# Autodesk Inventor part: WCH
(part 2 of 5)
hole "Díra1151" diameter "d10358" = 8.19608; stored, may be unused: countersink angle "d10362" = 90 deg, drill point angle "d10364" = 0 deg; dims "d10356" = 351, "d10357" = 76, "d10359" = 6, "d10360" = 4, "d10361" = 2, "d10363" = 8
hole "Díra1152" diameter "d10367" = 8.47059; stored, may be unused: countersink angle "d10371" = 90 deg, drill point angle "d10373" = 0 deg; dims "d10365" = 10, "d10366" = 87, "d10368" = 6, "d10369" = 4, "d10370" = 2, "d10372" = 8
hole "Díra1153" diameter "d10376" = 9.01961; stored, may be unused: countersink angle "d10380" = 90 deg, drill point angle "d10382" = 0 deg; dims "d10374" = 21, "d10375" = 87, "d10377" = 6, "d10378" = 4, "d10379" = 2, "d10381" = 8
hole "Díra1154" diameter "d10385" = 9.84314; stored, may be unused: countersink angle "d10389" = 90 deg, drill point angle "d10391" = 0 deg; dims "d10383" = 32, "d10384" = 87, "d10386" = 6, "d10387" = 4, "d10388" = 2, "d10390" = 8
hole "Díra1155" diameter "d10394" = 10; stored, may be unused: countersink angle "d10398" = 90 deg, drill point angle "d10400" = 0 deg; dims "d10392" = 43, "d10393" = 87, "d10395" = 6, "d10396" = 4, "d10397" = 2, "d10399" = 8
hole "Díra1156" diameter "d10403" = 10; stored, may be unused: countersink angle "d10407" = 90 deg, drill point angle "d10409" = 0 deg; dims "d10401" = 54, "d10402" = 87, "d10404" = 6, "d10405" = 4, "d10406" = 2, "d10408" = 8
hole "Díra1157" diameter "d10412" = 10; stored, may be unused: countersink angle "d10416" = 90 deg, drill point angle "d10418" = 0 deg; dims "d10410" = 65, "d10411" = 87, "d10413" = 6, "d10414" = 4, "d10415" = 2, "d10417" = 8
hole "Díra1158" diameter "d10421" = 10; stored, may be unused: countersink angle "d10425" = 90 deg, drill point angle "d10427" = 0 deg; dims "d10419" = 76, "d10420" = 87, "d10422" = 6, "d10423" = 4, "d10424" = 2, "d10426" = 8
hole "Díra1159" diameter "d10430" = 10; stored, may be unused: countersink angle "d10434" = 90 deg, drill point angle "d10436" = 0 deg; dims "d10428" = 87, "d10429" = 87, "d10431" = 6, "d10432" = 4, "d10433" = 2, "d10435" = 8
hole "Díra1160" diameter "d10439" = 10; stored, may be unused: countersink angle "d10443" = 90 deg, drill point angle "d10445" = 0 deg; dims "d10437" = 98, "d10438" = 87, "d10440" = 6, "d10441" = 4, "d10442" = 2, "d10444" = 8
hole "Díra1161" diameter "d10448" = 10; stored, may be unused: countersink angle "d10452" = 90 deg, drill point angle "d10454" = 0 deg; dims "d10446" = 109, "d10447" = 87, "d10449" = 6, "d10450" = 4, "d10451" = 2, "d10453" = 8
hole "Díra1162" diameter "d10457" = 10; stored, may be unused: countersink angle "d10461" = 90 deg, drill point angle "d10463" = 0 deg; dims "d10455" = 120, "d10456" = 87, "d10458" = 6, "d10459" = 4, "d10460" = 2, "d10462" = 8
hole "Díra1163" diameter "d10466" = 8.98039; stored, may be unused: countersink angle "d10470" = 90 deg, drill point angle "d10472" = 0 deg; dims "d10464" = 131, "d10465" = 87, "d10467" = 6, "d10468" = 4, "d10469" = 2, "d10471" = 8
hole "Díra1164" diameter "d10475" = 5.92157; stored, may be unused: countersink angle "d10479" = 90 deg, drill point angle "d10481" = 0 deg; dims "d10473" = 142, "d10474" = 87, "d10476" = 6, "d10477" = 4, "d10478" = 2, "d10480" = 8
hole "Díra1165" diameter "d10484" = 6.54902; stored, may be unused: countersink angle "d10488" = 90 deg, drill point angle "d10490" = 0 deg; dims "d10482" = 153, "d10483" = 87, "d10485" = 6, "d10486" = 4, "d10487" = 2, "d10489" = 8
hole "Díra1166" diameter "d10493" = 3.96078; stored, may be unused: countersink angle "d10497" = 90 deg, drill point angle "d10499" = 0 deg; dims "d10491" = 164, "d10492" = 87, "d10494" = 6, "d10495" = 4, "d10496" = 2, "d10498" = 8
hole "Díra1167" diameter "d10502" = 1.09804; stored, may be unused: countersink angle "d10506" = 90 deg, drill point angle "d10508" = 0 deg; dims "d10500" = 175, "d10501" = 87, "d10503" = 6, "d10504" = 4, "d10505" = 2, "d10507" = 8
hole "Díra1168" diameter "d10511" = 0.5098; stored, may be unused: countersink angle "d10515" = 90 deg, drill point angle "d10517" = 0 deg; dims "d10509" = 186, "d10510" = 87, "d10512" = 6, "d10513" = 4, "d10514" = 2, "d10516" = 8
hole "Díra1169" diameter "d10520" = 1.33333; stored, may be unused: countersink angle "d10524" = 90 deg, drill point angle "d10526" = 0 deg; dims "d10518" = 197, "d10519" = 87, "d10521" = 6, "d10522" = 4, "d10523" = 2, "d10525" = 8
hole "Díra1170" diameter "d10529" = 2.39216; stored, may be unused: countersink angle "d10533" = 90 deg, drill point angle "d10535" = 0 deg; dims "d10527" = 208, "d10528" = 87, "d10530" = 6, "d10531" = 4, "d10532" = 2, "d10534" = 8
hole "Díra1171" diameter "d10538" = 3.72549; stored, may be unused: countersink angle "d10542" = 90 deg, drill point angle "d10544" = 0 deg; dims "d10536" = 219, "d10537" = 87, "d10539" = 6, "d10540" = 4, "d10541" = 2, "d10543" = 8
hole "Díra1172" diameter "d10547" = 6; stored, may be unused: countersink angle "d10551" = 90 deg, drill point angle "d10553" = 0 deg; dims "d10545" = 230, "d10546" = 87, "d10548" = 6, "d10549" = 4, "d10550" = 2, "d10552" = 8
hole "Díra1173" diameter "d10556" = 1.13725; stored, may be unused: countersink angle "d10560" = 90 deg, drill point angle "d10562" = 0 deg; dims "d10554" = 241, "d10555" = 87, "d10557" = 6, "d10558" = 4, "d10559" = 2, "d10561" = 8
hole "Díra1174" diameter "d10565" = 1.13725; stored, may be unused: countersink angle "d10569" = 90 deg, drill point angle "d10571" = 0 deg; dims "d10563" = 252, "d10564" = 87, "d10566" = 6, "d10567" = 4, "d10568" = 2, "d10570" = 8
hole "Díra1175" diameter "d10574" = 7.56863; stored, may be unused: countersink angle "d10578" = 90 deg, drill point angle "d10580" = 0 deg; dims "d10572" = 263, "d10573" = 87, "d10575" = 6, "d10576" = 4, "d10577" = 2, "d10579" = 8
hole "Díra1176" diameter "d10583" = 10; stored, may be unused: countersink angle "d10587" = 90 deg, drill point angle "d10589" = 0 deg; dims "d10581" = 274, "d10582" = 87, "d10584" = 6, "d10585" = 4, "d10586" = 2, "d10588" = 8
hole "Díra1177" diameter "d10592" = 10; stored, may be unused: countersink angle "d10596" = 90 deg, drill point angle "d10598" = 0 deg; dims "d10590" = 285, "d10591" = 87, "d10593" = 6, "d10594" = 4, "d10595" = 2, "d10597" = 8
hole "Díra1178" diameter "d10601" = 9.92157; stored, may be unused: countersink angle "d10605" = 90 deg, drill point angle "d10607" = 0 deg; dims "d10599" = 296, "d10600" = 87, "d10602" = 6, "d10603" = 4, "d10604" = 2, "d10606" = 8
hole "Díra1179" diameter "d10610" = 9.2549; stored, may be unused: countersink angle "d10614" = 90 deg, drill point angle "d10616" = 0 deg; dims "d10608" = 307, "d10609" = 87, "d10611" = 6, "d10612" = 4, "d10613" = 2, "d10615" = 8
hole "Díra1180" diameter "d10619" = 8.58823; stored, may be unused: countersink angle "d10623" = 90 deg, drill point angle "d10625" = 0 deg; dims "d10617" = 318, "d10618" = 87, "d10620" = 6, "d10621" = 4, "d10622" = 2, "d10624" = 8
hole "Díra1181" diameter "d10628" = 7.41176; stored, may be unused: countersink angle "d10632" = 90 deg, drill point angle "d10634" = 0 deg; dims "d10626" = 329, "d10627" = 87, "d10629" = 6, "d10630" = 4, "d10631" = 2, "d10633" = 8
hole "Díra1182" diameter "d10637" = 6.7451; stored, may be unused: countersink angle "d10641" = 90 deg, drill point angle "d10643" = 0 deg; dims "d10635" = 340, "d10636" = 87, "d10638" = 6, "d10639" = 4, "d10640" = 2, "d10642" = 8
hole "Díra1183" diameter "d10646" = 8.43137; stored, may be unused: countersink angle "d10650" = 90 deg, drill point angle "d10652" = 0 deg; dims "d10644" = 351, "d10645" = 87, "d10647" = 6, "d10648" = 4, "d10649" = 2, "d10651" = 8
hole "Díra1184" diameter "d10655" = 6.66667; stored, may be unused: countersink angle "d10659" = 90 deg, drill point angle "d10661" = 0 deg; dims "d10653" = 10, "d10654" = 98, "d10656" = 6, "d10657" = 4, "d10658" = 2, "d10660" = 8
hole "Díra1185" diameter "d10664" = 8.47059; stored, may be unused: countersink angle "d10668" = 90 deg, drill point angle "d10670" = 0 deg; dims "d10662" = 21, "d10663" = 98, "d10665" = 6, "d10666" = 4, "d10667" = 2, "d10669" = 8
hole "Díra1186" diameter "d10673" = 10; stored, may be unused: countersink angle "d10677" = 90 deg, drill point angle "d10679" = 0 deg; dims "d10671" = 32, "d10672" = 98, "d10674" = 6, "d10675" = 4, "d10676" = 2, "d10678" = 8
hole "Díra1187" diameter "d10682" = 10; stored, may be unused: countersink angle "d10686" = 90 deg, drill point angle "d10688" = 0 deg; dims "d10680" = 43, "d10681" = 98, "d10683" = 6, "d10684" = 4, "d10685" = 2, "d10687" = 8
hole "Díra1188" diameter "d10691" = 10; stored, may be unused: countersink angle "d10695" = 90 deg, drill point angle "d10697" = 0 deg; dims "d10689" = 54, "d10690" = 98, "d10692" = 6, "d10693" = 4, "d10694" = 2, "d10696" = 8
hole "Díra1189" diameter "d10700" = 10; stored, may be unused: countersink angle "d10704" = 90 deg, drill point angle "d10706" = 0 deg; dims "d10698" = 65, "d10699" = 98, "d10701" = 6, "d10702" = 4, "d10703" = 2, "d10705" = 8
hole "Díra1190" diameter "d10709" = 10; stored, may be unused: countersink angle "d10713" = 90 deg, drill point angle "d10715" = 0 deg; dims "d10707" = 76, "d10708" = 98, "d10710" = 6, "d10711" = 4, "d10712" = 2, "d10714" = 8
hole "Díra1191" diameter "d10718" = 10; stored, may be unused: countersink angle "d10722" = 90 deg, drill point angle "d10724" = 0 deg; dims "d10716" = 87, "d10717" = 98, "d10719" = 6, "d10720" = 4, "d10721" = 2, "d10723" = 8
hole "Díra1192" diameter "d10727" = 10; stored, may be unused: countersink angle "d10731" = 90 deg, drill point angle "d10733" = 0 deg; dims "d10725" = 98, "d10726" = 98, "d10728" = 6, "d10729" = 4, "d10730" = 2, "d10732" = 8
hole "Díra1193" diameter "d10736" = 10; stored, may be unused: countersink angle "d10740" = 90 deg, drill point angle "d10742" = 0 deg; dims "d10734" = 109, "d10735" = 98, "d10737" = 6, "d10738" = 4, "d10739" = 2, "d10741" = 8
hole "Díra1194" diameter "d10745" = 8.90196; stored, may be unused: countersink angle "d10749" = 90 deg, drill point angle "d10751" = 0 deg; dims "d10743" = 120, "d10744" = 98, "d10746" = 6, "d10747" = 4, "d10748" = 2, "d10750" = 8
hole "Díra1195" diameter "d10754" = 5.84314; stored, may be unused: countersink angle "d10758" = 90 deg, drill point angle "d10760" = 0 deg; dims "d10752" = 131, "d10753" = 98, "d10755" = 6, "d10756" = 4, "d10757" = 2, "d10759" = 8
hole "Díra1196" diameter "d10763" = 5.68628; stored, may be unused: countersink angle "d10767" = 90 deg, drill point angle "d10769" = 0 deg; dims "d10761" = 142, "d10762" = 98, "d10764" = 6, "d10765" = 4, "d10766" = 2, "d10768" = 8
hole "Díra1197" diameter "d10772" = 4.07843; stored, may be unused: countersink angle "d10776" = 90 deg, drill point angle "d10778" = 0 deg; dims "d10770" = 153, "d10771" = 98, "d10773" = 6, "d10774" = 4, "d10775" = 2, "d10777" = 8
hole "Díra1198" diameter "d10781" = 1.01961; stored, may be unused: countersink angle "d10785" = 90 deg, drill point angle "d10787" = 0 deg; dims "d10779" = 164, "d10780" = 98, "d10782" = 6, "d10783" = 4, "d10784" = 2, "d10786" = 8
hole "Díra1199" diameter "d10790" = 0.07843; stored, may be unused: countersink angle "d10794" = 90 deg, drill point angle "d10796" = 0 deg; dims "d10788" = 175, "d10789" = 98, "d10791" = 6, "d10792" = 4, "d10793" = 2, "d10795" = 8
hole "Díra1200" diameter "d10799" = 0.27451; stored, may be unused: countersink angle "d10803" = 90 deg, drill point angle "d10805" = 0 deg; dims "d10797" = 186, "d10798" = 98, "d10800" = 6, "d10801" = 4, "d10802" = 2, "d10804" = 8
hole "Díra1201" diameter "d10808" = 1.4902; stored, may be unused: countersink angle "d10812" = 90 deg, drill point angle "d10814" = 0 deg; dims "d10806" = 197, "d10807" = 98, "d10809" = 6, "d10810" = 4, "d10811" = 2, "d10813" = 8
hole "Díra1202" diameter "d10817" = 5.09804; stored, may be unused: countersink angle "d10821" = 90 deg, drill point angle "d10823" = 0 deg; dims "d10815" = 208, "d10816" = 98, "d10818" = 6, "d10819" = 4, "d10820" = 2, "d10822" = 8
hole "Díra1203" diameter "d10826" = 7.68628; stored, may be unused: countersink angle "d10830" = 90 deg, drill point angle "d10832" = 0 deg; dims "d10824" = 219, "d10825" = 98, "d10827" = 6, "d10828" = 4, "d10829" = 2, "d10831" = 8
hole "Díra1204" diameter "d10835" = 6.15686; stored, may be unused: countersink angle "d10839" = 90 deg, drill point angle "d10841" = 0 deg; dims "d10833" = 230, "d10834" = 98, "d10836" = 6, "d10837" = 4, "d10838" = 2, "d10840" = 8
hole "Díra1205" diameter "d10844" = 0.31372; stored, may be unused: countersink angle "d10848" = 90 deg, drill point angle "d10850" = 0 deg; dims "d10842" = 241, "d10843" = 98, "d10845" = 6, "d10846" = 4, "d10847" = 2, "d10849" = 8
hole "Díra1206" diameter "d10853" = 2.19608; stored, may be unused: countersink angle "d10857" = 90 deg, drill point angle "d10859" = 0 deg; dims "d10851" = 252, "d10852" = 98, "d10854" = 6, "d10855" = 4, "d10856" = 2, "d10858" = 8
hole "Díra1207" diameter "d10862" = 7.15033; stored, may be unused: countersink angle "d10866" = 90 deg, drill point angle "d10868" = 0 deg; dims "d10860" = 263, "d10861" = 98, "d10863" = 6, "d10864" = 4, "d10865" = 2, "d10867" = 8
hole "Díra1208" diameter "d10871" = 9.80392; stored, may be unused: countersink angle "d10875" = 90 deg, drill point angle "d10877" = 0 deg; dims "d10869" = 274, "d10870" = 98, "d10872" = 6, "d10873" = 4, "d10874" = 2, "d10876" = 8
hole "Díra1209" diameter "d10880" = 10; stored, may be unused: countersink angle "d10884" = 90 deg, drill point angle "d10886" = 0 deg; dims "d10878" = 285, "d10879" = 98, "d10881" = 6, "d10882" = 4, "d10883" = 2, "d10885" = 8
hole "Díra1210" diameter "d10889" = 10; stored, may be unused: countersink angle "d10893" = 90 deg, drill point angle "d10895" = 0 deg; dims "d10887" = 296, "d10888" = 98, "d10890" = 6, "d10891" = 4, "d10892" = 2, "d10894" = 8
hole "Díra1211" diameter "d10898" = 9.29412; stored, may be unused: countersink angle "d10902" = 90 deg, drill point angle "d10904" = 0 deg; dims "d10896" = 307, "d10897" = 98, "d10899" = 6, "d10900" = 4, "d10901" = 2, "d10903" = 8
hole "Díra1212" diameter "d10907" = 8.54902; stored, may be unused: countersink angle "d10911" = 90 deg, drill point angle "d10913" = 0 deg; dims "d10905" = 318, "d10906" = 98, "d10908" = 6, "d10909" = 4, "d10910" = 2, "d10912" = 8
hole "Díra1213" diameter "d10916" = 6.11765; stored, may be unused: countersink angle "d10920" = 90 deg, drill point angle "d10922" = 0 deg; dims "d10914" = 329, "d10915" = 98, "d10917" = 6, "d10918" = 4, "d10919" = 2, "d10921" = 8
hole "Díra1214" diameter "d10925" = 4.58824; stored, may be unused: countersink angle "d10929" = 90 deg, drill point angle "d10931" = 0 deg; dims "d10923" = 340, "d10924" = 98, "d10926" = 6, "d10927" = 4, "d10928" = 2, "d10930" = 8
hole "Díra1215" diameter "d10934" = 7.68628; stored, may be unused: countersink angle "d10938" = 90 deg, drill point angle "d10940" = 0 deg; dims "d10932" = 351, "d10933" = 98, "d10935" = 6, "d10936" = 4, "d10937" = 2, "d10939" = 8
hole "Díra1216" diameter "d10943" = 6.90196; stored, may be unused: countersink angle "d10947" = 90 deg, drill point angle "d10949" = 0 deg; dims "d10941" = 10, "d10942" = 109, "d10944" = 6, "d10945" = 4, "d10946" = 2, "d10948" = 8
hole "Díra1217" diameter "d10952" = 6.64052; stored, may be unused: countersink angle "d10956" = 90 deg, drill point angle "d10958" = 0 deg; dims "d10950" = 21, "d10951" = 109, "d10953" = 6, "d10954" = 4, "d10955" = 2, "d10957" = 8
hole "Díra1218" diameter "d10961" = 9.80392; stored, may be unused: countersink angle "d10965" = 90 deg, drill point angle "d10967" = 0 deg; dims "d10959" = 32, "d10960" = 109, "d10962" = 6, "d10963" = 4, "d10964" = 2, "d10966" = 8
hole "Díra1219" diameter "d10970" = 10; stored, may be unused: countersink angle "d10974" = 90 deg, drill point angle "d10976" = 0 deg; dims "d10968" = 43, "d10969" = 109, "d10971" = 6, "d10972" = 4, "d10973" = 2, "d10975" = 8
hole "Díra1220" diameter "d10979" = 10; stored, may be unused: countersink angle "d10983" = 90 deg, drill point angle "d10985" = 0 deg; dims "d10977" = 54, "d10978" = 109, "d10980" = 6, "d10981" = 4, "d10982" = 2, "d10984" = 8
hole "Díra1221" diameter "d10988" = 10; stored, may be unused: countersink angle "d10992" = 90 deg, drill point angle "d10994" = 0 deg; dims "d10986" = 65, "d10987" = 109, "d10989" = 6, "d10990" = 4, "d10991" = 2, "d10993" = 8
hole "Díra1222" diameter "d10997" = 10; stored, may be unused: countersink angle "d11001" = 90 deg, drill point angle "d11003" = 0 deg; dims "d10995" = 76, "d10996" = 109, "d10998" = 6, "d10999" = 4, "d11000" = 2, "d11002" = 8
hole "Díra1223" diameter "d11006" = 10; stored, may be unused: countersink angle "d11010" = 90 deg, drill point angle "d11012" = 0 deg; dims "d11004" = 87, "d11005" = 109, "d11007" = 6, "d11008" = 4, "d11009" = 2, "d11011" = 8
hole "Díra1224" diameter "d11015" = 10; stored, may be unused: countersink angle "d11019" = 90 deg, drill point angle "d11021" = 0 deg; dims "d11013" = 98, "d11014" = 109, "d11016" = 6, "d11017" = 4, "d11018" = 2, "d11020" = 8
hole "Díra1225" diameter "d11024" = 8.82353; stored, may be unused: countersink angle "d11028" = 90 deg, drill point angle "d11030" = 0 deg; dims "d11022" = 109, "d11023" = 109, "d11025" = 6, "d11026" = 4, "d11027" = 2, "d11029" = 8
hole "Díra1226" diameter "d11033" = 5.88235; stored, may be unused: countersink angle "d11037" = 90 deg, drill point angle "d11039" = 0 deg; dims "d11031" = 120, "d11032" = 109, "d11034" = 6, "d11035" = 4, "d11036" = 2, "d11038" = 8
hole "Díra1227" diameter "d11042" = 4.66667; stored, may be unused: countersink angle "d11046" = 90 deg, drill point angle "d11048" = 0 deg; dims "d11040" = 131, "d11041" = 109, "d11043" = 6, "d11044" = 4, "d11045" = 2, "d11047" = 8
hole "Díra1228" diameter "d11051" = 4.15686; stored, may be unused: countersink angle "d11055" = 90 deg, drill point angle "d11057" = 0 deg; dims "d11049" = 142, "d11050" = 109, "d11052" = 6, "d11053" = 4, "d11054" = 2, "d11056" = 8
hole "Díra1229" diameter "d11060" = 3.09804; stored, may be unused: countersink angle "d11064" = 90 deg, drill point angle "d11066" = 0 deg; dims "d11058" = 153, "d11059" = 109, "d11061" = 6, "d11062" = 4, "d11063" = 2, "d11065" = 8
hole "Díra1230" diameter "d11069" = 0.82353; stored, may be unused: countersink angle "d11073" = 90 deg, drill point angle "d11075" = 0 deg; dims "d11067" = 164, "d11068" = 109, "d11070" = 6, "d11071" = 4, "d11072" = 2, "d11074" = 8
hole "Díra1231" diameter "d11078" = 1.2549; stored, may be unused: countersink angle "d11082" = 90 deg, drill point angle "d11084" = 0 deg; dims "d11076" = 175, "d11077" = 109, "d11079" = 6, "d11080" = 4, "d11081" = 2, "d11083" = 8
hole "Díra1232" diameter "d11087" = 3.80392; stored, may be unused: countersink angle "d11091" = 90 deg, drill point angle "d11093" = 0 deg; dims "d11085" = 186, "d11086" = 109, "d11088" = 6, "d11089" = 4, "d11090" = 2, "d11092" = 8
hole "Díra1233" diameter "d11096" = 4.47059; stored, may be unused: countersink angle "d11100" = 90 deg, drill point angle "d11102" = 0 deg; dims "d11094" = 197, "d11095" = 109, "d11097" = 6, "d11098" = 4, "d11099" = 2, "d11101" = 8
hole "Díra1234" diameter "d11105" = 2.90196; stored, may be unused: countersink angle "d11109" = 90 deg, drill point angle "d11111" = 0 deg; dims "d11103" = 208, "d11104" = 109, "d11106" = 6, "d11107" = 4, "d11108" = 2, "d11110" = 8
hole "Díra1235" diameter "d11114" = 7.68628; stored, may be unused: countersink angle "d11118" = 90 deg, drill point angle "d11120" = 0 deg; dims "d11112" = 219, "d11113" = 109, "d11115" = 6, "d11116" = 4, "d11117" = 2, "d11119" = 8
hole "Díra1236" diameter "d11123" = 5.68628; stored, may be unused: countersink angle "d11127" = 90 deg, drill point angle "d11129" = 0 deg; dims "d11121" = 230, "d11122" = 109, "d11124" = 6, "d11125" = 4, "d11126" = 2, "d11128" = 8
hole "Díra1237" diameter "d11132" = 0.66667; stored, may be unused: countersink angle "d11136" = 90 deg, drill point angle "d11138" = 0 deg; dims "d11130" = 241, "d11131" = 109, "d11133" = 6, "d11134" = 4, "d11135" = 2, "d11137" = 8
hole "Díra1238" diameter "d11141" = 3.97386; stored, may be unused: countersink angle "d11145" = 90 deg, drill point angle "d11147" = 0 deg; dims "d11139" = 252, "d11140" = 109, "d11142" = 6, "d11143" = 4, "d11144" = 2, "d11146" = 8
hole "Díra1239" diameter "d11150" = 6.47059; stored, may be unused: countersink angle "d11154" = 90 deg, drill point angle "d11156" = 0 deg; dims "d11148" = 263, "d11149" = 109, "d11151" = 6, "d11152" = 4, "d11153" = 2, "d11155" = 8
hole "Díra1240" diameter "d11159" = 7.96078; stored, may be unused: countersink angle "d11163" = 90 deg, drill point angle "d11165" = 0 deg; dims "d11157" = 274, "d11158" = 109, "d11160" = 6, "d11161" = 4, "d11162" = 2, "d11164" = 8
hole "Díra1241" diameter "d11168" = 10; stored, may be unused: countersink angle "d11172" = 90 deg, drill point angle "d11174" = 0 deg; dims "d11166" = 285, "d11167" = 109, "d11169" = 6, "d11170" = 4, "d11171" = 2, "d11173" = 8
hole "Díra1242" diameter "d11177" = 9.45098; stored, may be unused: countersink angle "d11181" = 90 deg, drill point angle "d11183" = 0 deg; dims "d11175" = 296, "d11176" = 109, "d11178" = 6, "d11179" = 4, "d11180" = 2, "d11182" = 8
hole "Díra1243" diameter "d11186" = 8.98039; stored, may be unused: countersink angle "d11190" = 90 deg, drill point angle "d11192" = 0 deg; dims "d11184" = 307, "d11185" = 109, "d11187" = 6, "d11188" = 4, "d11189" = 2, "d11191" = 8
hole "Díra1244" diameter "d11195" = 7.00654; stored, may be unused: countersink angle "d11199" = 90 deg, drill point angle "d11201" = 0 deg; dims "d11193" = 318, "d11194" = 109, "d11196" = 6, "d11197" = 4, "d11198" = 2, "d11200" = 8
hole "Díra1245" diameter "d11204" = 3.72549; stored, may be unused: countersink angle "d11208" = 90 deg, drill point angle "d11210" = 0 deg; dims "d11202" = 329, "d11203" = 109, "d11205" = 6, "d11206" = 4, "d11207" = 2, "d11209" = 8
hole "Díra1246" diameter "d11213" = 7.41176; stored, may be unused: countersink angle "d11217" = 90 deg, drill point angle "d11219" = 0 deg; dims "d11211" = 340, "d11212" = 109, "d11214" = 6, "d11215" = 4, "d11216" = 2, "d11218" = 8
hole "Díra1247" diameter "d11222" = 9.2549; stored, may be unused: countersink angle "d11226" = 90 deg, drill point angle "d11228" = 0 deg; dims "d11220" = 351, "d11221" = 109, "d11223" = 6, "d11224" = 4, "d11225" = 2, "d11227" = 8
hole "Díra1248" diameter "d11231" = 7.41176; stored, may be unused: countersink angle "d11235" = 90 deg, drill point angle "d11237" = 0 deg; dims "d11229" = 10, "d11230" = 120, "d11232" = 6, "d11233" = 4, "d11234" = 2, "d11236" = 8
hole "Díra1249" diameter "d11240" = 6.7451; stored, may be unused: countersink angle "d11244" = 90 deg, drill point angle "d11246" = 0 deg; dims "d11238" = 21, "d11239" = 120, "d11241" = 6, "d11242" = 4, "d11243" = 2, "d11245" = 8
hole "Díra1250" diameter "d11249" = 8.90196; stored, may be unused: countersink angle "d11253" = 90 deg, drill point angle "d11255" = 0 deg; dims "d11247" = 32, "d11248" = 120, "d11250" = 6, "d11251" = 4, "d11252" = 2, "d11254" = 8
hole "Díra1251" diameter "d11258" = 10; stored, may be unused: countersink angle "d11262" = 90 deg, drill point angle "d11264" = 0 deg; dims "d11256" = 43, "d11257" = 120, "d11259" = 6, "d11260" = 4, "d11261" = 2, "d11263" = 8
hole "Díra1252" diameter "d11267" = 10; stored, may be unused: countersink angle "d11271" = 90 deg, drill point angle "d11273" = 0 deg; dims "d11265" = 54, "d11266" = 120, "d11268" = 6, "d11269" = 4, "d11270" = 2, "d11272" = 8
hole "Díra1253" diameter "d11276" = 10; stored, may be unused: countersink angle "d11280" = 90 deg, drill point angle "d11282" = 0 deg; dims "d11274" = 65, "d11275" = 120, "d11277" = 6, "d11278" = 4, "d11279" = 2, "d11281" = 8
hole "Díra1254" diameter "d11285" = 10; stored, may be unused: countersink angle "d11289" = 90 deg, drill point angle "d11291" = 0 deg; dims "d11283" = 76, "d11284" = 120, "d11286" = 6, "d11287" = 4, "d11288" = 2, "d11290" = 8
hole "Díra1255" diameter "d11294" = 10; stored, may be unused: countersink angle "d11298" = 90 deg, drill point angle "d11300" = 0 deg; dims "d11292" = 87, "d11293" = 120, "d11295" = 6, "d11296" = 4, "d11297" = 2, "d11299" = 8
hole "Díra1256" diameter "d11303" = 9.80392; stored, may be unused: countersink angle "d11307" = 90 deg, drill point angle "d11309" = 0 deg; dims "d11301" = 98, "d11302" = 120, "d11304" = 6, "d11305" = 4, "d11306" = 2, "d11308" = 8
hole "Díra1257" diameter "d11312" = 5.52941; stored, may be unused: countersink angle "d11316" = 90 deg, drill point angle "d11318" = 0 deg; dims "d11310" = 109, "d11311" = 120, "d11313" = 6, "d11314" = 4, "d11315" = 2, "d11317" = 8
hole "Díra1258" diameter "d11321" = 5.33333; stored, may be unused: countersink angle "d11325" = 90 deg, drill point angle "d11327" = 0 deg; dims "d11319" = 120, "d11320" = 120, "d11322" = 6, "d11323" = 4, "d11324" = 2, "d11326" = 8
hole "Díra1259" diameter "d11330" = 3.17647; stored, may be unused: countersink angle "d11334" = 90 deg, drill point angle "d11336" = 0 deg; dims "d11328" = 131, "d11329" = 120, "d11331" = 6, "d11332" = 4, "d11333" = 2, "d11335" = 8
hole "Díra1260" diameter "d11339" = 2.35294; stored, may be unused: countersink angle "d11343" = 90 deg, drill point angle "d11345" = 0 deg; dims "d11337" = 142, "d11338" = 120, "d11340" = 6, "d11341" = 4, "d11342" = 2, "d11344" = 8
hole "Díra1261" diameter "d11348" = 3.01961; stored, may be unused: countersink angle "d11352" = 90 deg, drill point angle "d11354" = 0 deg; dims "d11346" = 153, "d11347" = 120, "d11349" = 6, "d11350" = 4, "d11351" = 2, "d11353" = 8
hole "Díra1262" diameter "d11357" = 0.86275; stored, may be unused: countersink angle "d11361" = 90 deg, drill point angle "d11363" = 0 deg; dims "d11355" = 164, "d11356" = 120, "d11358" = 6, "d11359" = 4, "d11360" = 2, "d11362" = 8
hole "Díra1263" diameter "d11366" = 1.13725; stored, may be unused: countersink angle "d11370" = 90 deg, drill point angle "d11372" = 0 deg; dims "d11364" = 175, "d11365" = 120, "d11367" = 6, "d11368" = 4, "d11369" = 2, "d11371" = 8
hole "Díra1264" diameter "d11375" = 1.68628; stored, may be unused: countersink angle "d11379" = 90 deg, drill point angle "d11381" = 0 deg; dims "d11373" = 186, "d11374" = 120, "d11376" = 6, "d11377" = 4, "d11378" = 2, "d11380" = 8
hole "Díra1265" diameter "d11384" = 0.66667; stored, may be unused: countersink angle "d11388" = 90 deg, drill point angle "d11390" = 0 deg; dims "d11382" = 197, "d11383" = 120, "d11385" = 6, "d11386" = 4, "d11387" = 2, "d11389" = 8
hole "Díra1266" diameter "d11393" = 2.98039; stored, may be unused: countersink angle "d11397" = 90 deg, drill point angle "d11399" = 0 deg; dims "d11391" = 208, "d11392" = 120, "d11394" = 6, "d11395" = 4, "d11396" = 2, "d11398" = 8
hole "Díra1267" diameter "d11402" = 4.90196; stored, may be unused: countersink angle "d11406" = 90 deg, drill point angle "d11408" = 0 deg; dims "d11400" = 219, "d11401" = 120, "d11403" = 6, "d11404" = 4, "d11405" = 2, "d11407" = 8
hole "Díra1268" diameter "d11411" = 1.84314; stored, may be unused: countersink angle "d11415" = 90 deg, drill point angle "d11417" = 0 deg; dims "d11409" = 230, "d11410" = 120, "d11412" = 6, "d11413" = 4, "d11414" = 2, "d11416" = 8
hole "Díra1269" diameter "d11420" = 1.33333; stored, may be unused: countersink angle "d11424" = 90 deg, drill point angle "d11426" = 0 deg; dims "d11418" = 241, "d11419" = 120, "d11421" = 6, "d11422" = 4, "d11423" = 2, "d11425" = 8
hole "Díra1270" diameter "d11429" = 3.29412; stored, may be unused: countersink angle "d11433" = 90 deg, drill point angle "d11435" = 0 deg; dims "d11427" = 252, "d11428" = 120, "d11430" = 6, "d11431" = 4, "d11432" = 2, "d11434" = 8
hole "Díra1271" diameter "d11438" = 2.70588; stored, may be unused: countersink angle "d11442" = 90 deg, drill point angle "d11444" = 0 deg; dims "d11436" = 263, "d11437" = 120, "d11439" = 6, "d11440" = 4, "d11441" = 2, "d11443" = 8
hole "Díra1272" diameter "d11447" = 3.80392; stored, may be unused: countersink angle "d11451" = 90 deg, drill point angle "d11453" = 0 deg; dims "d11445" = 274, "d11446" = 120, "d11448" = 6, "d11449" = 4, "d11450" = 2, "d11452" = 8
hole "Díra1273" diameter "d11456" = 10; stored, may be unused: countersink angle "d11460" = 90 deg, drill point angle "d11462" = 0 deg; dims "d11454" = 285, "d11455" = 120, "d11457" = 6, "d11458" = 4, "d11459" = 2, "d11461" = 8
hole "Díra1274" diameter "d11465" = 9.29412; stored, may be unused: countersink angle "d11469" = 90 deg, drill point angle "d11471" = 0 deg; dims "d11463" = 296, "d11464" = 120, "d11466" = 6, "d11467" = 4, "d11468" = 2, "d11470" = 8
hole "Díra1275" diameter "d11474" = 7.80392; stored, may be unused: countersink angle "d11478" = 90 deg, drill point angle "d11480" = 0 deg; dims "d11472" = 307, "d11473" = 120, "d11475" = 6, "d11476" = 4, "d11477" = 2, "d11479" = 8
hole "Díra1276" diameter "d11483" = 3.29412; stored, may be unused: countersink angle "d11487" = 90 deg, drill point angle "d11489" = 0 deg; dims "d11481" = 318, "d11482" = 120, "d11484" = 6, "d11485" = 4, "d11486" = 2, "d11488" = 8
hole "Díra1277" diameter "d11492" = 7.17647; stored, may be unused: countersink angle "d11496" = 90 deg, drill point angle "d11498" = 0 deg; dims "d11490" = 329, "d11491" = 120, "d11493" = 6, "d11494" = 4, "d11495" = 2, "d11497" = 8
hole "Díra1278" diameter "d11501" = 9.45098; stored, may be unused: countersink angle "d11505" = 90 deg, drill point angle "d11507" = 0 deg; dims "d11499" = 340, "d11500" = 120, "d11502" = 6, "d11503" = 4, "d11504" = 2, "d11506" = 8
hole "Díra1279" diameter "d11510" = 8.19608; stored, may be unused: countersink angle "d11514" = 90 deg, drill point angle "d11516" = 0 deg; dims "d11508" = 351, "d11509" = 120, "d11511" = 6, "d11512" = 4, "d11513" = 2, "d11515" = 8
hole "Díra1280" diameter "d11519" = 6.27451; stored, may be unused: countersink angle "d11523" = 90 deg, drill point angle "d11525" = 0 deg; dims "d11517" = 10, "d11518" = 131, "d11520" = 6, "d11521" = 4, "d11522" = 2, "d11524" = 8
hole "Díra1281" diameter "d11528" = 5.68628; stored, may be unused: countersink angle "d11532" = 90 deg, drill point angle "d11534" = 0 deg; dims "d11526" = 21, "d11527" = 131, "d11529" = 6, "d11530" = 4, "d11531" = 2, "d11533" = 8
hole "Díra1282" diameter "d11537" = 7.17647; stored, may be unused: countersink angle "d11541" = 90 deg, drill point angle "d11543" = 0 deg; dims "d11535" = 32, "d11536" = 131, "d11538" = 6, "d11539" = 4, "d11540" = 2, "d11542" = 8
hole "Díra1283" diameter "d11546" = 10; stored, may be unused: countersink angle "d11550" = 90 deg, drill point angle "d11552" = 0 deg; dims "d11544" = 43, "d11545" = 131, "d11547" = 6, "d11548" = 4, "d11549" = 2, "d11551" = 8
hole "Díra1284" diameter "d11555" = 10; stored, may be unused: countersink angle "d11559" = 90 deg, drill point angle "d11561" = 0 deg; dims "d11553" = 54, "d11554" = 131, "d11556" = 6, "d11557" = 4, "d11558" = 2, "d11560" = 8
hole "Díra1285" diameter "d11564" = 10; stored, may be unused: countersink angle "d11568" = 90 deg, drill point angle "d11570" = 0 deg; dims "d11562" = 65, "d11563" = 131, "d11565" = 6, "d11566" = 4, "d11567" = 2, "d11569" = 8
hole "Díra1286" diameter "d11573" = 10; stored, may be unused: countersink angle "d11577" = 90 deg, drill point angle "d11579" = 0 deg; dims "d11571" = 76, "d11572" = 131, "d11574" = 6, "d11575" = 4, "d11576" = 2, "d11578" = 8
hole "Díra1287" diameter "d11582" = 10; stored, may be unused: countersink angle "d11586" = 90 deg, drill point angle "d11588" = 0 deg; dims "d11580" = 87, "d11581" = 131, "d11583" = 6, "d11584" = 4, "d11585" = 2, "d11587" = 8
hole "Díra1288" diameter "d11591" = 7.60784; stored, may be unused: countersink angle "d11595" = 90 deg, drill point angle "d11597" = 0 deg; dims "d11589" = 98, "d11590" = 131, "d11592" = 6, "d11593" = 4, "d11594" = 2, "d11596" = 8
hole "Díra1289" diameter "d11600" = 5.09804; stored, may be unused: countersink angle "d11604" = 90 deg, drill point angle "d11606" = 0 deg; dims "d11598" = 109, "d11599" = 131, "d11601" = 6, "d11602" = 4, "d11603" = 2, "d11605" = 8
hole "Díra1290" diameter "d11609" = 4; stored, may be unused: countersink angle "d11613" = 90 deg, drill point angle "d11615" = 0 deg; dims "d11607" = 120, "d11608" = 131, "d11610" = 6, "d11611" = 4, "d11612" = 2, "d11614" = 8
hole "Díra1291" diameter "d11618" = 2.5098; stored, may be unused: countersink angle "d11622" = 90 deg, drill point angle "d11624" = 0 deg; dims "d11616" = 131, "d11617" = 131, "d11619" = 6, "d11620" = 4, "d11621" = 2, "d11623" = 8
hole "Díra1292" diameter "d11627" = 1.33333; stored, may be unused: countersink angle "d11631" = 90 deg, drill point angle "d11633" = 0 deg; dims "d11625" = 142, "d11626" = 131, "d11628" = 6, "d11629" = 4, "d11630" = 2, "d11632" = 8
hole "Díra1293" diameter "d11636" = 2.39216; stored, may be unused: countersink angle "d11640" = 90 deg, drill point angle "d11642" = 0 deg; dims "d11634" = 153, "d11635" = 131, "d11637" = 6, "d11638" = 4, "d11639" = 2, "d11641" = 8
hole "Díra1294" diameter "d11645" = 3.01961; stored, may be unused: countersink angle "d11649" = 90 deg, drill point angle "d11651" = 0 deg; dims "d11643" = 164, "d11644" = 131, "d11646" = 6, "d11647" = 4, "d11648" = 2, "d11650" = 8
hole "Díra1295" diameter "d11654" = 3.17647; stored, may be unused: countersink angle "d11658" = 90 deg, drill point angle "d11660" = 0 deg; dims "d11652" = 175, "d11653" = 131, "d11655" = 6, "d11656" = 4, "d11657" = 2, "d11659" = 8
hole "Díra1296" diameter "d11663" = 5.05882; stored, may be unused: countersink angle "d11667" = 90 deg, drill point angle "d11669" = 0 deg; dims "d11661" = 186, "d11662" = 131, "d11664" = 6, "d11665" = 4, "d11666" = 2, "d11668" = 8
hole "Díra1297" diameter "d11672" = 6.35294; stored, may be unused: countersink angle "d11676" = 90 deg, drill point angle "d11678" = 0 deg; dims "d11670" = 197, "d11671" = 131, "d11673" = 6, "d11674" = 4, "d11675" = 2, "d11677" = 8
hole "Díra1298" diameter "d11681" = 7.80392; stored, may be unused: countersink angle "d11685" = 90 deg, drill point angle "d11687" = 0 deg; dims "d11679" = 208, "d11680" = 131, "d11682" = 6, "d11683" = 4, "d11684" = 2, "d11686" = 8
hole "Díra1299" diameter "d11690" = 6.98039; stored, may be unused: countersink angle "d11694" = 90 deg, drill point angle "d11696" = 0 deg; dims "d11688" = 219, "d11689" = 131, "d11691" = 6, "d11692" = 4, "d11693" = 2, "d11695" = 8
hole "Díra1300" diameter "d11699" = 3.29412; stored, may be unused: countersink angle "d11703" = 90 deg, drill point angle "d11705" = 0 deg; dims "d11697" = 230, "d11698" = 131, "d11700" = 6, "d11701" = 4, "d11702" = 2, "d11704" = 8
hole "Díra1301" diameter "d11708" = 6.47059; stored, may be unused: countersink angle "d11712" = 90 deg, drill point angle "d11714" = 0 deg; dims "d11706" = 241, "d11707" = 131, "d11709" = 6, "d11710" = 4, "d11711" = 2, "d11713" = 8
hole "Díra1302" diameter "d11717" = 4.47059; stored, may be unused: countersink angle "d11721" = 90 deg, drill point angle "d11723" = 0 deg; dims "d11715" = 252, "d11716" = 131, "d11718" = 6, "d11719" = 4, "d11720" = 2, "d11722" = 8
hole "Díra1303" diameter "d11726" = 1.33333; stored, may be unused: countersink angle "d11730" = 90 deg, drill point angle "d11732" = 0 deg; dims "d11724" = 263, "d11725" = 131, "d11727" = 6, "d11728" = 4, "d11729" = 2, "d11731" = 8
hole "Díra1304" diameter "d11735" = 1.60784; stored, may be unused: countersink angle "d11739" = 90 deg, drill point angle "d11741" = 0 deg; dims "d11733" = 274, "d11734" = 131, "d11736" = 6, "d11737" = 4, "d11738" = 2, "d11740" = 8
hole "Díra1305" diameter "d11744" = 8.62745; stored, may be unused: countersink angle "d11748" = 90 deg, drill point angle "d11750" = 0 deg; dims "d11742" = 285, "d11743" = 131, "d11745" = 6, "d11746" = 4, "d11747" = 2, "d11749" = 8
hole "Díra1306" diameter "d11753" = 8.62745; stored, may be unused: countersink angle "d11757" = 90 deg, drill point angle "d11759" = 0 deg; dims "d11751" = 296, "d11752" = 131, "d11754" = 6, "d11755" = 4, "d11756" = 2, "d11758" = 8
hole "Díra1307" diameter "d11762" = 3.4902; stored, may be unused: countersink angle "d11766" = 90 deg, drill point angle "d11768" = 0 deg; dims "d11760" = 307, "d11761" = 131, "d11763" = 6, "d11764" = 4, "d11765" = 2, "d11767" = 8
hole "Díra1308" diameter "d11771" = 6.19608; stored, may be unused: countersink angle "d11775" = 90 deg, drill point angle "d11777" = 0 deg; dims "d11769" = 318, "d11770" = 131, "d11772" = 6, "d11773" = 4, "d11774" = 2, "d11776" = 8
hole "Díra1309" diameter "d11780" = 8.54902; stored, may be unused: countersink angle "d11784" = 90 deg, drill point angle "d11786" = 0 deg; dims "d11778" = 329, "d11779" = 131, "d11781" = 6, "d11782" = 4, "d11783" = 2, "d11785" = 8
hole "Díra1310" diameter "d11789" = 6.35294; stored, may be unused: countersink angle "d11793" = 90 deg, drill point angle "d11795" = 0 deg; dims "d11787" = 340, "d11788" = 131, "d11790" = 6, "d11791" = 4, "d11792" = 2, "d11794" = 8
hole "Díra1311" diameter "d11798" = 2.7451; stored, may be unused: countersink angle "d11802" = 90 deg, drill point angle "d11804" = 0 deg; dims "d11796" = 351, "d11797" = 131, "d11799" = 6, "d11800" = 4, "d11801" = 2, "d11803" = 8
hole "Díra1312" diameter "d11807" = 4.35294; stored, may be unused: countersink angle "d11811" = 90 deg, drill point angle "d11813" = 0 deg; dims "d11805" = 10, "d11806" = 142, "d11808" = 6, "d11809" = 4, "d11810" = 2, "d11812" = 8
hole "Díra1313" diameter "d11816" = 3.33333; stored, may be unused: countersink angle "d11820" = 90 deg, drill point angle "d11822" = 0 deg; dims "d11814" = 21, "d11815" = 142, "d11817" = 6, "d11818" = 4, "d11819" = 2, "d11821" = 8
hole "Díra1314" diameter "d11825" = 3.41176; stored, may be unused: countersink angle "d11829" = 90 deg, drill point angle "d11831" = 0 deg; dims "d11823" = 32, "d11824" = 142, "d11826" = 6, "d11827" = 4, "d11828" = 2, "d11830" = 8
hole "Díra1315" diameter "d11834" = 9.41177; stored, may be unused: countersink angle "d11838" = 90 deg, drill point angle "d11840" = 0 deg; dims "d11832" = 43, "d11833" = 142, "d11835" = 6, "d11836" = 4, "d11837" = 2, "d11839" = 8
hole "Díra1316" diameter "d11843" = 10; stored, may be unused: countersink angle "d11847" = 90 deg, drill point angle "d11849" = 0 deg; dims "d11841" = 54, "d11842" = 142, "d11844" = 6, "d11845" = 4, "d11846" = 2, "d11848" = 8
hole "Díra1317" diameter "d11852" = 10; stored, may be unused: countersink angle "d11856" = 90 deg, drill point angle "d11858" = 0 deg; dims "d11850" = 65, "d11851" = 142, "d11853" = 6, "d11854" = 4, "d11855" = 2, "d11857" = 8
hole "Díra1318" diameter "d11861" = 9.41177; stored, may be unused: countersink angle "d11865" = 90 deg, drill point angle "d11867" = 0 deg; dims "d11859" = 76, "d11860" = 142, "d11862" = 6, "d11863" = 4, "d11864" = 2, "d11866" = 8
hole "Díra1319" diameter "d11870" = 10; stored, may be unused: countersink angle "d11874" = 90 deg, drill point angle "d11876" = 0 deg; dims "d11868" = 87, "d11869" = 142, "d11871" = 6, "d11872" = 4, "d11873" = 2, "d11875" = 8
hole "Díra1320" diameter "d11879" = 5.68628; stored, may be unused: countersink angle "d11883" = 90 deg, drill point angle "d11885" = 0 deg; dims "d11877" = 98, "d11878" = 142, "d11880" = 6, "d11881" = 4, "d11882" = 2, "d11884" = 8
hole "Díra1321" diameter "d11888" = 3.84314; stored, may be unused: countersink angle "d11892" = 90 deg, drill point angle "d11894" = 0 deg; dims "d11886" = 109, "d11887" = 142, "d11889" = 6, "d11890" = 4, "d11891" = 2, "d11893" = 8
hole "Díra1322" diameter "d11897" = 2.69281; stored, may be unused: countersink angle "d11901" = 90 deg, drill point angle "d11903" = 0 deg; dims "d11895" = 120, "d11896" = 142, "d11898" = 6, "d11899" = 4, "d11900" = 2, "d11902" = 8
hole "Díra1323" diameter "d11906" = 1.72549; stored, may be unused: countersink angle "d11910" = 90 deg, drill point angle "d11912" = 0 deg; dims "d11904" = 131, "d11905" = 142, "d11907" = 6, "d11908" = 4, "d11909" = 2, "d11911" = 8
hole "Díra1324" diameter "d11915" = 1.2549; stored, may be unused: countersink angle "d11919" = 90 deg, drill point angle "d11921" = 0 deg; dims "d11913" = 142, "d11914" = 142, "d11916" = 6, "d11917" = 4, "d11918" = 2, "d11920" = 8
hole "Díra1325" diameter "d11924" = 3.33333; stored, may be unused: countersink angle "d11928" = 90 deg, drill point angle "d11930" = 0 deg; dims "d11922" = 153, "d11923" = 142, "d11925" = 6, "d11926" = 4, "d11927" = 2, "d11929" = 8
hole "Díra1326" diameter "d11933" = 6; stored, may be unused: countersink angle "d11937" = 90 deg, drill point angle "d11939" = 0 deg; dims "d11931" = 164, "d11932" = 142, "d11934" = 6, "d11935" = 4, "d11936" = 2, "d11938" = 8
hole "Díra1327" diameter "d11942" = 5.41177; stored, may be unused: countersink angle "d11946" = 90 deg, drill point angle "d11948" = 0 deg; dims "d11940" = 175, "d11941" = 142, "d11943" = 6, "d11944" = 4, "d11945" = 2, "d11947" = 8
hole "Díra1328" diameter "d11951" = 3.09804; stored, may be unused: countersink angle "d11955" = 90 deg, drill point angle "d11957" = 0 deg; dims "d11949" = 186, "d11950" = 142, "d11952" = 6, "d11953" = 4, "d11954" = 2, "d11956" = 8
hole "Díra1329" diameter "d11960" = 3.13726; stored, may be unused: countersink angle "d11964" = 90 deg, drill point angle "d11966" = 0 deg; dims "d11958" = 197, "d11959" = 142, "d11961" = 6, "d11962" = 4, "d11963" = 2, "d11965" = 8
hole "Díra1330" diameter "d11969" = 3.17647; stored, may be unused: countersink angle "d11973" = 90 deg, drill point angle "d11975" = 0 deg; dims "d11967" = 208, "d11968" = 142, "d11970" = 6, "d11971" = 4, "d11972" = 2, "d11974" = 8
hole "Díra1331" diameter "d11978" = 2.54902; stored, may be unused: countersink angle "d11982" = 90 deg, drill point angle "d11984" = 0 deg; dims "d11976" = 219, "d11977" = 142, "d11979" = 6, "d11980" = 4, "d11981" = 2, "d11983" = 8
hole "Díra1332" diameter "d11987" = 1.72549; stored, may be unused: countersink angle "d11991" = 90 deg, drill point angle "d11993" = 0 deg; dims "d11985" = 230, "d11986" = 142, "d11988" = 6, "d11989" = 4, "d11990" = 2, "d11992" = 8
hole "Díra1333" diameter "d11996" = 2.11765; stored, may be unused: countersink angle "d12000" = 90 deg, drill point angle "d12002" = 0 deg; dims "d11994" = 241, "d11995" = 142, "d11997" = 6, "d11998" = 4, "d11999" = 2, "d12001" = 8
hole "Díra1334" diameter "d12005" = 5.05882; stored, may be unused: countersink angle "d12009" = 90 deg, drill point angle "d12011" = 0 deg; dims "d12003" = 252, "d12004" = 142, "d12006" = 6, "d12007" = 4, "d12008" = 2, "d12010" = 8
hole "Díra1335" diameter "d12014" = 2.70588; stored, may be unused: countersink angle "d12018" = 90 deg, drill point angle "d12020" = 0 deg; dims "d12012" = 263, "d12013" = 142, "d12015" = 6, "d12016" = 4, "d12017" = 2, "d12019" = 8
hole "Díra1336" diameter "d12023" = 0.66667; stored, may be unused: countersink angle "d12027" = 90 deg, drill point angle "d12029" = 0 deg; dims "d12021" = 274, "d12022" = 142, "d12024" = 6, "d12025" = 4, "d12026" = 2, "d12028" = 8
hole "Díra1337" diameter "d12032" = 5.52941; stored, may be unused: countersink angle "d12036" = 90 deg, drill point angle "d12038" = 0 deg; dims "d12030" = 285, "d12031" = 142, "d12033" = 6, "d12034" = 4, "d12035" = 2, "d12037" = 8
hole "Díra1338" diameter "d12041" = 6.07843; stored, may be unused: countersink angle "d12045" = 90 deg, drill point angle "d12047" = 0 deg; dims "d12039" = 296, "d12040" = 142, "d12042" = 6, "d12043" = 4, "d12044" = 2, "d12046" = 8
hole "Díra1339" diameter "d12050" = 3.64706; stored, may be unused: countersink angle "d12054" = 90 deg, drill point angle "d12056" = 0 deg; dims "d12048" = 307, "d12049" = 142, "d12051" = 6, "d12052" = 4, "d12053" = 2, "d12055" = 8
hole "Díra1340" diameter "d12059" = 5.4902; stored, may be unused: countersink angle "d12063" = 90 deg, drill point angle "d12065" = 0 deg; dims "d12057" = 318, "d12058" = 142, "d12060" = 6, "d12061" = 4, "d12062" = 2, "d12064" = 8
hole "Díra1341" diameter "d12068" = 2.19608; stored, may be unused: countersink angle "d12072" = 90 deg, drill point angle "d12074" = 0 deg; dims "d12066" = 329, "d12067" = 142, "d12069" = 6, "d12070" = 4, "d12071" = 2, "d12073" = 8
hole "Díra1342" diameter "d12077" = 1.64706; stored, may be unused: countersink angle "d12081" = 90 deg, drill point angle "d12083" = 0 deg; dims "d12075" = 340, "d12076" = 142, "d12078" = 6, "d12079" = 4, "d12080" = 2, "d12082" = 8
hole "Díra1343" diameter "d12086" = 2.19608; stored, may be unused: countersink angle "d12090" = 90 deg, drill point angle "d12092" = 0 deg; dims "d12084" = 351, "d12085" = 142, "d12087" = 6, "d12088" = 4, "d12089" = 2, "d12091" = 8
hole "Díra1344" diameter "d12095" = 3.56863; stored, may be unused: countersink angle "d12099" = 90 deg, drill point angle "d12101" = 0 deg; dims "d12093" = 10, "d12094" = 153, "d12096" = 6, "d12097" = 4, "d12098" = 2, "d12100" = 8
hole "Díra1345" diameter "d12104" = 2.98039; stored, may be unused: countersink angle "d12108" = 90 deg, drill point angle "d12110" = 0 deg; dims "d12102" = 21, "d12103" = 153, "d12105" = 6, "d12106" = 4, "d12107" = 2, "d12109" = 8
hole "Díra1346" diameter "d12113" = 2.5098; stored, may be unused: countersink angle "d12117" = 90 deg, drill point angle "d12119" = 0 deg; dims "d12111" = 32, "d12112" = 153, "d12114" = 6, "d12115" = 4, "d12116" = 2, "d12118" = 8
hole "Díra1347" diameter "d12122" = 7.21569; stored, may be unused: countersink angle "d12126" = 90 deg, drill point angle "d12128" = 0 deg; dims "d12120" = 43, "d12121" = 153, "d12123" = 6, "d12124" = 4, "d12125" = 2, "d12127" = 8
hole "Díra1348" diameter "d12131" = 10; stored, may be unused: countersink angle "d12135" = 90 deg, drill point angle "d12137" = 0 deg; dims "d12129" = 54, "d12130" = 153, "d12132" = 6, "d12133" = 4, "d12134" = 2, "d12136" = 8
hole "Díra1349" diameter "d12140" = 7.01961; stored, may be unused: countersink angle "d12144" = 90 deg, drill point angle "d12146" = 0 deg; dims "d12138" = 65, "d12139" = 153, "d12141" = 6, "d12142" = 4, "d12143" = 2, "d12145" = 8
hole "Díra1350" diameter "d12149" = 10; stored, may be unused: countersink angle "d12153" = 90 deg, drill point angle "d12155" = 0 deg; dims "d12147" = 76, "d12148" = 153, "d12150" = 6, "d12151" = 4, "d12152" = 2, "d12154" = 8
hole "Díra1351" diameter "d12158" = 9.76471; stored, may be unused: countersink angle "d12162" = 90 deg, drill point angle "d12164" = 0 deg; dims "d12156" = 87, "d12157" = 153, "d12159" = 6, "d12160" = 4, "d12161" = 2, "d12163" = 8
hole "Díra1352" diameter "d12167" = 3.56863; stored, may be unused: countersink angle "d12171" = 90 deg, drill point angle "d12173" = 0 deg; dims "d12165" = 98, "d12166" = 153, "d12168" = 6, "d12169" = 4, "d12170" = 2, "d12172" = 8
hole "Díra1353" diameter "d12176" = 2.7451; stored, may be unused: countersink angle "d12180" = 90 deg, drill point angle "d12182" = 0 deg; dims "d12174" = 109, "d12175" = 153, "d12177" = 6, "d12178" = 4, "d12179" = 2, "d12181" = 8
hole "Díra1354" diameter "d12185" = 2.19608; stored, may be unused: countersink angle "d12189" = 90 deg, drill point angle "d12191" = 0 deg; dims "d12183" = 120, "d12184" = 153, "d12186" = 6, "d12187" = 4, "d12188" = 2, "d12190" = 8
hole "Díra1355" diameter "d12194" = 3.4902; stored, may be unused: countersink angle "d12198" = 90 deg, drill point angle "d12200" = 0 deg; dims "d12192" = 131, "d12193" = 153, "d12195" = 6, "d12196" = 4, "d12197" = 2, "d12199" = 8
hole "Díra1356" diameter "d12203" = 5.64706; stored, may be unused: countersink angle "d12207" = 90 deg, drill point angle "d12209" = 0 deg; dims "d12201" = 142, "d12202" = 153, "d12204" = 6, "d12205" = 4, "d12206" = 2, "d12208" = 8
hole "Díra1357" diameter "d12212" = 7.37255; stored, may be unused: countersink angle "d12216" = 90 deg, drill point angle "d12218" = 0 deg; dims "d12210" = 153, "d12211" = 153, "d12213" = 6, "d12214" = 4, "d12215" = 2, "d12217" = 8
hole "Díra1358" diameter "d12221" = 5.88235; stored, may be unused: countersink angle "d12225" = 90 deg, drill point angle "d12227" = 0 deg; dims "d12219" = 164, "d12220" = 153, "d12222" = 6, "d12223" = 4, "d12224" = 2, "d12226" = 8
hole "Díra1359" diameter "d12230" = 2.31372; stored, may be unused: countersink angle "d12234" = 90 deg, drill point angle "d12236" = 0 deg; dims "d12228" = 175, "d12229" = 153, "d12231" = 6, "d12232" = 4, "d12233" = 2, "d12235" = 8
hole "Díra1360" diameter "d12239" = 2.19608; stored, may be unused: countersink angle "d12243" = 90 deg, drill point angle "d12245" = 0 deg; dims "d12237" = 186, "d12238" = 153, "d12240" = 6, "d12241" = 4, "d12242" = 2, "d12244" = 8
hole "Díra1361" diameter "d12248" = 3.76471; stored, may be unused: countersink angle "d12252" = 90 deg, drill point angle "d12254" = 0 deg; dims "d12246" = 197, "d12247" = 153, "d12249" = 6, "d12250" = 4, "d12251" = 2, "d12253" = 8
hole "Díra1362" diameter "d12257" = 6.90196; stored, may be unused: countersink angle "d12261" = 90 deg, drill point angle "d12263" = 0 deg; dims "d12255" = 208, "d12256" = 153, "d12258" = 6, "d12259" = 4, "d12260" = 2, "d12262" = 8
hole "Díra1363" diameter "d12266" = 5.88235; stored, may be unused: countersink angle "d12270" = 90 deg, drill point angle "d12272" = 0 deg; dims "d12264" = 219, "d12265" = 153, "d12267" = 6, "d12268" = 4, "d12269" = 2, "d12271" = 8
hole "Díra1364" diameter "d12275" = 1.29412; stored, may be unused: countersink angle "d12279" = 90 deg, drill point angle "d12281" = 0 deg; dims "d12273" = 230, "d12274" = 153, "d12276" = 6, "d12277" = 4, "d12278" = 2, "d12280" = 8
